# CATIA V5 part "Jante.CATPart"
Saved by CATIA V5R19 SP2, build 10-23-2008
Part number: Jante
Bounding box of the stored display mesh (mm): x -239.933 to 239.933, y -980.382 to -740, z -239.967 to 239.967
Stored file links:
  G:\EU_thinkMotion\CFAO_2010\MMS_groupe3\MMS_groupe3\pmayet\pmayet_assemblage_animation\pmayet_assemblage_animation\Jante.CATPart
  G:\EU_thinkMotion\CFAO_2010\MMS_groupe3\MMS_groupe3\pmayet\pmayet_assemblage_animation\pmayet_assemblage_animation\pmayet_assemblage_animation.CATProduct
  G:\EU_thinkMotion\CFAO_2010\MMS_groupe3\MMS_groupe3\pmayet\pmayet_assemblage_animation\pmayet_assemblage_animation\Squelette_porte_moyeu.CATPart
  G:\EU_thinkMotion\CFAO_2010\MMS_groupe3\MMS_groupe3\pmayet\pmayet_assemblage_animation\pmayet_assemblage_animation\Moyeu.CATPart
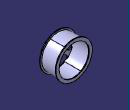
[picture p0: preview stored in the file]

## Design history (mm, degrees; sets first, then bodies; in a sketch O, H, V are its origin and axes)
Parameters
  Epaisseur_jante = 10 mm
  Rayon_jante = 200 mm
  Longueur_jante = 210 mm
Set1
  Plane1: linked copy from another document
  Plane2: linked copy from another document
  DatumCurve1: linked copy from another document
  Point1: linked copy from another document
  Plane3: linked copy from another document
Body1 (main body)
  Sketch1 on Plane1, origin (0, 0, 0), H (0, 1, 0), V (0, 0, 1)
    point P1 (-960, 0)
    spline S1 through (-960, 0) (-970, 100) (-960, 200)
    reference intersected line E1 through (0, 0) direction (-1, 0) from Plane2
    reference intersected line E2 through (0, 0) direction (-1, 0) from Plane2
    reference projected line E3 (-945, 70) -> (-945, -70) from edge of DatumCurve1
    reference projected line E4 (-945, 70) -> (-945, -70) from edge of DatumCurve1
    reference projected line E5 (-945, 70) -> (-945, -70) from edge of DatumCurve1
    spline S2 through (-970, 0) (-980, 120) (-960, 240)
    reference intersected line E6 through (0, 0) direction (-1, 0) from Plane2
    reference intersected line E7 through (0, 0) direction (-1, 0) from Plane2
    reference intersected line E8 through (0, 0) direction (-1, 0) from Plane2
    reference projected line E9 (-945, 70) -> (-945, -70) from edge of DatumCurve1
    reference projected line E10 (-945, 70) -> (-945, -70) from edge of DatumCurve1
    line L1 (-970, 0) -> (-960, 0)
    point P2 (-970, 0)
    point P3 (-960, 0)
    line L2 (-960, 240) -> (-949.5, 240)
    point P4 (-960, 240)
    point P5 (-949.5, 240)
    line L3 (-960, 200) -> (-750, 200)
    point P6 (-960, 200)
    point P7 (-750, 200)
    line L4 (-949.5, 240) -> (-949.5, 220)
    point P8 (-949.5, 240)
    point P9 (-949.5, 220)
    line L5 (-750, 200) -> (-750, 200)
    point P10 (-750, 200)
    point P11 (-750, 200)
    line L6 (-750, 200) -> (-740, 200)
    point P12 (-750, 200)
    point P13 (-740, 200)
    line L7 (-740, 240) -> (-740, 200)
    point P14 (-740, 240)
    point P15 (-740, 200)
    line L8 (-949.5, 220) -> (-750.5, 220)
    point P16 (-949.5, 220)
    point P17 (-750.5, 220)
    line L9 (-750.5, 240) -> (-740, 240)
    point P18 (-750.5, 240)
    point P19 (-740, 240)
    reference projected point E11 (-800, 0) from Point1
    line L10 (-750.5, 240) -> (-750.5, 220)
    point P20 (-750.5, 240)
    point P21 (-750.5, 220)
    axis line L11 (-1080, 0) -> (-1020, 0)
    point P22 (-1080, 0)
    point P24 (-960, 0)
    point P25 (-960, 200)
    point P26 (-970, 100)
    point P27 (-970, 0)
    point P28 (-980, 120)
    point P29 (-960, 240)
    distance E1 P25 = 200 {= Rayon_jante}
    distance E2 P26 = 100 {= Rayon_jante /2}
    distance P24 E3 = 15
    distance P25 E4 = 15
    distance P26 E5 = 25
    distance P27 P24 = 10 {= Epaisseur_jante}
    distance P28 E7 = 120 {= Rayon_jante / 2 + Epaisseur_jante *2}
    distance P29 E8 = 240 {= Rayon_jante + Epaisseur_jante *4}
    distance P29 E9 = 15 {= 15mm}
    distance P28 E10 = 35 {= Epaisseur_jante + 25mm}
    length L2 = 10.5 {= Longueur_jante *0.05}
    distance P9 L3 = 20 {= Epaisseur_jante *2}
    length L3 = 210 {= Longueur_jante}
    length L5 = 0
    length L6 = 10 {= Epaisseur_jante}
    length L9 = 10.5 {= Longueur_jante *0.05}
    distance E11 L9 = 240 {= Rayon_jante + Epaisseur_jante *4}
    distance L3 P21 = 20 {= Epaisseur_jante *2}
    distance P17 P21 = 0
    coincidence: P1 H, P24 P1, E6 P27, P27 P2, P3 P24, P29 P4, P6 P25, P8 P5, P11 P7, P12 P10, P13 P15, P9 P16, P19 P14, P20 P18, P22 L1
    horizontal: L1 H, L2 H, L3 H, L6 H, L8 H, L9 H, L11 H
    vertical: L4 V, L5 V, L7 V, L10 V
  Shaft1: profile Sketch1, axis Sketch1.L11, angle 360
  Sketch2 on Plane3, origin (0, -800, 0), H (-1, 0, 0), V (0, 0, 1)
    arc A1 centre (0, 0) radius 66.6667 from (-44.6297, 49.5241) to (-62.6365, 22.8279) ccw
    point P1 (0, 0)
    point P2 (-44.6297, 49.5241)
    point P3 (-62.6365, 22.8279)
    reference projected point E1 (0, 0) from Point1
    arc A2 centre (0, 0) radius 200 from (-125.5288, 155.7001) to (-191.3865, 58.062) ccw
    point P4 (0, 0)
    point P5 (-91.3598, 177.914)
    point P6 (-199.183, 18.0596)
    reference projected point E2 (0, 0) from Point1
    line L1 (-161.6316, 19.3709) -> (-62.6365, 22.8279)
    point P7 (-199.183, 18.0596)
    point P8 (-62.6365, 22.8279)
    line L2 (-78.5087, 142.6057) -> (-44.6297, 49.5241)
    point P9 (-91.3598, 177.914)
    point P10 (-44.6297, 49.5241)
    reference intersected line E5 through (0, 0) direction (0, -1) from Plane1
    reference projected point E6 (0, 0) from Point1
    reference projected point E7 (0, 0) from Point1
    circle A3 centre (-13.6808, 37.5877) radius 10
    point P11 (-13.6808, 37.5877)
    reference projected point E8 (0, 0) from Point1
    arc A4 centre (-106.6995, 132.3451) radius 30 from (-125.5288, 155.7001) to (-78.5087, 142.6057) cw
    arc A5 centre (-162.6786, 49.3527) radius 30 from (-191.3865, 58.062) to (-161.6316, 19.3709) ccw
    radius A1 = 66.6667 {= Rayon_jante /3}
    radius A2 = 200 {= Rayon_jante}
    angle L1 L2 = 72
    angle E5 L2 = 20
    distance L1 E6 = 25
    distance E7 L2 = 25
    distance E8 P11 = 40 {= Rayon_jante /5}
    distance A3 P11 = 10 {= Rayon_jante /20}
    distance P11 L2 = 25
    radius A4 = 30
    radius A5 = 30
    coincidence: P1 E1, E2 P4, P7 P6, P8 P3, P5 P9, P10 P2, A2 P5, L2 P9, A2 P6, L1 P7
    tangency: A4 A2, A4 L2, A5 A2, A5 L1
  Pocket1: profile Sketch2, direction (0, -1, 0), through (limit type 3)
  CircPattern1: of Pocket1, instances 5, angular step 72, axis from face of Shaft1 from Sketch1.L8
Relations
  Sketch1.length(L5) = Epaisseur_jante *2 (deactivated)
